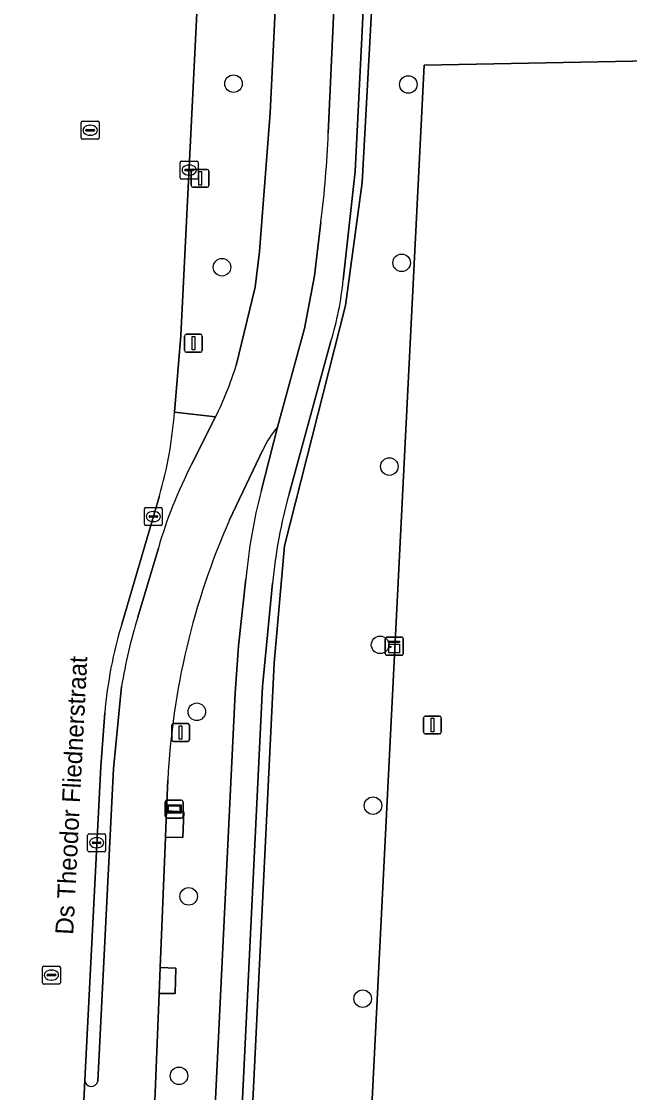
# Model space of a CAD drawing. Extents: x 161758 to 162722, y 384793 to 385405.
# Drawn here: x 162127.8 to 162161.7, y 385280.9 to 385340.7 of the extents above; entities that cross this region are included whole.
import ezdxf

# ---------------------------------------------------------------- set-up
doc = ezdxf.new("R2010")
doc.units = 0
for name, color, linetype in [('IMGEO_Berm_groen', 7, 'Continuous'), ('IMGEO_Boom', 7, 'Continuous'), ('IMGEO_Fietspad_gesloten', 7, 'Continuous'), ('IMGEO_Groenvoorziening', 7, 'Continuous'), ('IMGEO_Hek', 7, 'Continuous'), ('IMGEO_Kast', 7, 'Continuous'), ('IMGEO_Kolk', 7, 'Continuous'), ('IMGEO_Lichtmast', 7, 'Continuous'), ('IMGEO_Openbare_ruimte_label', 7, 'Continuous'), ('IMGEO_Rijbaan_lokaal_gesloten', 7, 'Continuous'), ('IMGEO_Rioolput', 7, 'Continuous'), ('IMGEO_Terreindeel_open', 7, 'Continuous'), ('IMGEO_Verkeersbordpaal', 7, 'Continuous'), ('IMGEO_Verkeerseiland_open', 7, 'Continuous'), ('IMGEO_Voetpad_open', 7, 'Continuous'), ('IMGEO_Wegwijzer', 7, 'Continuous')]:
    doc.layers.add(name, color=color, linetype=linetype)

msp = doc.modelspace()

# ---------------------------------------------------------------- linework, layer by layer
at = {"layer": 'IMGEO_Berm_groen'}
for points in [[(162138.352, 385356.061), (162138.078, 385350.894), (162136.706, 385323.145), (162136.346, 385318.869), (162138.638, 385318.607)], [(162139.783, 385321.485), (162140.845, 385325.839), (162141.092, 385327.83), (162141.672, 385335.573), (162142.271, 385347.778)], [(162141.17, 385314.469), (162142.089, 385318.047)], [(162141.277, 385316.771), (162139.414, 385312.866)], [(162139.724, 385303.205), (162139.916, 385305.842), (162140.326, 385309.592)], [(162135.97, 385298.369), (162135.902, 385296.656), (162136.872, 385296.597), (162136.811, 385295.159), (162135.843, 385295.176), (162135.553, 385287.905), (162136.417, 385287.87), (162136.38, 385286.457), (162135.496, 385286.459), (162135.129, 385277.251), (162134.787, 385270.387), (162138.123, 385270.221), (162139.724, 385303.205)]]:
    msp.add_lwpolyline(points, dxfattribs=at)
for centre, radius, start, end in [((162120.972, 385327.302), 19.69, 333.79389, 342.81627), ((162146.167, 385314.556), 5.368, 139.43026, 155.62736), ((162172.317, 385306.567), 32.134, 165.76484, 174.59875), ((162176.927, 385296.297), 41.01, 156.16908, 177.10328)]:
    msp.add_arc(centre, radius, start, end, dxfattribs=at)
at = {"layer": 'IMGEO_Boom'}
for centre in [(162139.634, 385337.193), (162149.378, 385337.145), (162149.005, 385327.204), (162138.998, 385326.956), (162148.319, 385315.843), (162147.806, 385305.902), (162137.589, 385302.172), (162147.413, 385296.939), (162137.138, 385291.878), (162146.832, 385286.174), (162136.595, 385281.876)]:
    msp.add_circle(centre, 0.489, dxfattribs=at)
at = {"layer": 'IMGEO_Fietspad_gesloten'}
for points in [[(162144.918, 385334.435), (162145.502, 385347.426), (162145.726, 385349.837), (162142.207, 385350.248), (162142.271, 385347.778), (162141.672, 385335.573), (162141.092, 385327.83), (162140.845, 385325.839), (162139.783, 385321.485)], [(162142.089, 385318.047), (162143.594, 385323.536), (162144.145, 385326.47), (162144.509, 385329.468)], [(162138.638, 385318.607), (162137.294, 385315.952)], [(162139.414, 385312.866), (162141.277, 385316.771)], [(162135.45, 385311.302), (162134.299, 385307.45)], [(162133.395, 385303.575), (162132.954, 385298.991), (162132.066, 385281.578)], [(162132.096, 385277.332), (162135.129, 385277.251), (162135.496, 385286.459), (162135.553, 385287.905), (162135.843, 385295.176), (162135.902, 385296.656), (162135.97, 385298.369)], [(162131.344, 385281.63), (162131.151, 385277.397)]]:
    msp.add_lwpolyline(points, dxfattribs=at)
for centre, radius, start, end in [((162086.015, 385336.785), 58.95, 352.86997, 357.7154), ((162120.972, 385327.302), 19.69, 333.79389, 342.81627), ((162146.167, 385314.556), 5.368, 139.43026, 155.62736), ((162160.039, 385304.242), 25.582, 152.75806, 163.97943), ((162176.927, 385296.297), 41.01, 156.16908, 177.10328), ((162164.556, 385298.348), 31.596, 163.2582, 170.47843), ((162131.708, 385281.644), 0.364, 182.24351, 349.51758)]:
    msp.add_arc(centre, radius, start, end, dxfattribs=at)
at = {"layer": 'IMGEO_Groenvoorziening'}
for points in [[(162141.818, 385309.344), (162141.256, 385303.578), (162138.882, 385254.554), (162134.904, 385254.707), (162126.688, 385089.939), (162123.507, 385021.46), (162127.975, 385021.202), (162128.056, 385022.862), (162131.31, 385089.036), (162131.34, 385089.671), (162131.648, 385095.933), (162131.658, 385096.124), (162133.367, 385130.823), (162139.214, 385249.548), (162141.898, 385304.88), (162142.47, 385311.424), (162145.872, 385324.819), (162146.81, 385331.678), (162147.884, 385351.44), (162211.124, 385352.462)], [(162211.124, 385352.462), (162147.884, 385351.44), (162146.81, 385331.678), (162145.872, 385324.819), (162142.47, 385311.424), (162141.898, 385304.88), (162139.214, 385249.548), (162133.367, 385130.823), (162139.817, 385130.505), (162150.256, 385338.217), (162211.326, 385339.4)], [(162147.19, 385348.002), (162146.419, 385332.292), (162145.754, 385326.254)], [(162211.326, 385339.4), (162150.256, 385338.217), (162139.817, 385130.505), (162139.433, 385122.857), (162137.997, 385095.888), (162138.195, 385088.671), (162134.073, 385009.395), (162135.55, 385009.336), (162149.437, 385008.779), (162272.675, 385003.936)], [(162145.067, 385322.828), (162142.737, 385314.33)]]:
    msp.add_lwpolyline(points, dxfattribs=at)
for centre, radius, start, end in [((162127.687, 385328.095), 18.161, 343.14065, 354.1816), ((162169.832, 385306.758), 28.133, 164.38692, 174.72643)]:
    msp.add_arc(centre, radius, start, end, dxfattribs=at)
at = {"layer": 'IMGEO_Hek'}
msp.add_lwpolyline([(162147.884, 385351.44), (162146.81, 385331.678), (162145.872, 385324.819), (162142.47, 385311.424), (162141.898, 385304.88), (162139.214, 385249.548)], dxfattribs=at)
at = {"layer": 'IMGEO_Kast'}
for p, q in [((162148.097, 385305.402), (162148.097, 385306.243)), ((162148.097, 385306.243), (162148.097, 385305.402)), ((162148.172, 385306.327), (162149.013, 385306.327)), ((162149.013, 385306.327), (162148.172, 385306.327)), ((162149.097, 385306.252), (162149.097, 385305.411)), ((162149.097, 385305.411), (162149.097, 385306.252)), ((162149.022, 385305.327), (162148.181, 385305.327)), ((162148.181, 385305.327), (162149.022, 385305.327))]:
    msp.add_line(p, q, dxfattribs=at)
for points in [[(162148.292, 385306.117), (162148.892, 385306.117), (162148.892, 385306.032), (162148.292, 385306.032), (162148.292, 385306.117)], [(162148.292, 385305.942), (162148.892, 385305.942), (162148.892, 385305.453), (162148.292, 385305.453), (162148.292, 385305.942)]]:
    msp.add_lwpolyline(points, dxfattribs=at)
msp.add_circle((162148.376, 385305.791), 0.0377, dxfattribs=at)
for centre, start, end in [((162148.175, 385306.249), 92.4484, 184.28452), ((162148.175, 385306.249), 92.4484, 184.28452), ((162149.019, 385306.249), 2.4484, 94.28452), ((162149.019, 385306.249), 2.4484, 94.28452), ((162148.175, 385305.405), 182.4484, 274.28452), ((162148.175, 385305.405), 182.4484, 274.28452), ((162149.019, 385305.405), 272.4484, 4.28452), ((162149.019, 385305.405), 272.4484, 4.28452)]:
    msp.add_arc(centre, 0.0779, start, end, dxfattribs=at)
at = {"layer": 'IMGEO_Kolk'}
for p, q in [((162136.667, 385331.949), (162136.667, 385332.801)), ((162136.742, 385332.875), (162137.594, 385332.875)), ((162137.155, 385332.655), (162137.18, 385332.655)), ((162137.668, 385332.801), (162137.668, 385331.949)), ((162137.594, 385331.875), (162136.742, 385331.875)), ((162136.926, 385332.369), (162136.926, 385332.381)), ((162137.364, 385332.332), (162136.966, 385332.332)), ((162136.969, 385332.418), (162137.367, 385332.418)), ((162137.178, 385332.095), (162137.153, 385332.095)), ((162137.41, 385332.381), (162137.41, 385332.369)), ((162134.667, 385312.631), (162134.667, 385313.483)), ((162134.742, 385313.557), (162135.594, 385313.557)), ((162135.155, 385313.337), (162135.18, 385313.337)), ((162135.668, 385313.483), (162135.668, 385312.631)), ((162134.926, 385313.051), (162134.926, 385313.063)), ((162135.364, 385313.014), (162134.966, 385313.014)), ((162134.969, 385313.1), (162135.367, 385313.1)), ((162135.178, 385312.777), (162135.153, 385312.777)), ((162135.41, 385313.063), (162135.41, 385313.051)), ((162135.594, 385312.557), (162134.742, 385312.557)), ((162131.507, 385294.441), (162131.507, 385295.293)), ((162131.582, 385295.367), (162132.434, 385295.367)), ((162131.766, 385294.861), (162131.766, 385294.873)), ((162132.204, 385294.824), (162131.806, 385294.824)), ((162131.809, 385294.91), (162132.207, 385294.91)), ((162131.995, 385295.147), (162132.02, 385295.147)), ((162132.25, 385294.873), (162132.25, 385294.861)), ((162132.508, 385295.293), (162132.508, 385294.441)), ((162132.434, 385294.367), (162131.582, 385294.367)), ((162132.018, 385294.587), (162131.993, 385294.587))]:
    msp.add_line(p, q, dxfattribs=at)
for points in [[(162136.667, 385331.949), (162136.667, 385332.801)], [(162136.742, 385332.875), (162137.594, 385332.875)], [(162137.668, 385332.801), (162137.668, 385331.949)], [(162137.594, 385331.875), (162136.742, 385331.875)], [(162134.667, 385312.631), (162134.667, 385313.483)], [(162134.742, 385313.557), (162135.594, 385313.557)], [(162135.668, 385313.483), (162135.668, 385312.631)], [(162135.594, 385312.557), (162134.742, 385312.557)], [(162131.507, 385294.441), (162131.507, 385295.293)], [(162131.582, 385295.367), (162132.434, 385295.367)], [(162132.508, 385295.293), (162132.508, 385294.441)], [(162132.434, 385294.367), (162131.582, 385294.367)]]:
    msp.add_lwpolyline(points, dxfattribs=at)
for centre, radius, start, end in [((162136.744, 385332.799), 0.0765, 91.55205, 178.44795), ((162136.744, 385332.799), 0.0765, 91.55205, 178.44795), ((162137.592, 385332.799), 0.0765, 1.55205, 88.44795), ((162137.592, 385332.799), 0.0765, 1.55205, 88.44795), ((162136.744, 385331.951), 0.0765, 181.55205, 268.44795), ((162136.744, 385331.951), 0.0765, 181.55205, 268.44795), ((162136.966, 385332.378), 0.0403, 85.87752, 175.75265), ((162136.963, 385332.368), 0.0366, 178.93798, 274.71019), ((162137.367, 385332.375), 0.043, 264.86636, 352.45326), ((162137.371, 385332.38), 0.0386, 1.73085, 96.63898), ((162137.592, 385331.951), 0.0765, 271.55205, 358.44795), ((162137.592, 385331.951), 0.0765, 271.55205, 358.44795), ((162134.744, 385313.481), 0.0765, 91.55205, 178.44795), ((162134.744, 385313.481), 0.0765, 91.55205, 178.44795), ((162135.592, 385313.481), 0.0765, 1.55205, 88.44795), ((162135.592, 385313.481), 0.0765, 1.55205, 88.44795), ((162134.966, 385313.06), 0.0403, 85.87752, 175.75265), ((162134.963, 385313.05), 0.0366, 178.93798, 274.71019), ((162135.367, 385313.057), 0.043, 264.86636, 352.45326), ((162135.371, 385313.062), 0.0386, 1.73085, 96.63898), ((162134.744, 385312.633), 0.0765, 181.55205, 268.44795), ((162134.744, 385312.633), 0.0765, 181.55205, 268.44795), ((162135.592, 385312.633), 0.0765, 271.55205, 358.44795), ((162135.592, 385312.633), 0.0765, 271.55205, 358.44795), ((162131.584, 385295.291), 0.0765, 91.55205, 178.44795), ((162131.584, 385295.291), 0.0765, 91.55205, 178.44795), ((162131.806, 385294.87), 0.0403, 85.87752, 175.75265), ((162131.803, 385294.86), 0.0366, 178.93798, 274.71019), ((162132.207, 385294.867), 0.043, 264.86636, 352.45326), ((162132.211, 385294.872), 0.0386, 1.73085, 96.63898), ((162132.432, 385295.291), 0.0765, 1.55205, 88.44795), ((162132.432, 385295.291), 0.0765, 1.55205, 88.44795), ((162131.584, 385294.443), 0.0765, 181.55205, 268.44795), ((162131.584, 385294.443), 0.0765, 181.55205, 268.44795), ((162132.432, 385294.443), 0.0765, 271.55205, 358.44795), ((162132.432, 385294.443), 0.0765, 271.55205, 358.44795)]:
    msp.add_arc(centre, radius, start, end, dxfattribs=at)
for centre, major_axis, ratio, start_param, end_param in [((162137.154, 385332.375), (-0.387, 0.002), 0.722429, 4.712389, 7.853982), ((162137.179, 385332.375), (-0.39, 0.002), 0.717154, 1.570796, 4.712389), ((162135.154, 385313.057), (-0.387, 0.002), 0.722429, 4.712389, 7.853982), ((162135.179, 385313.057), (-0.39, 0.002), 0.717154, 1.570796, 4.712389), ((162131.994, 385294.867), (-0.387, 0.002), 0.722429, 4.712389, 7.853982), ((162132.019, 385294.867), (-0.39, 0.002), 0.717154, 1.570796, 4.712389)]:
    msp.add_ellipse(centre, major_axis=major_axis, ratio=ratio, start_param=start_param, end_param=end_param, dxfattribs=at)
at = {"layer": 'IMGEO_Lichtmast'}
for p, q in [((162136.907, 385322.318), (162136.907, 385323.118)), ((162136.907, 385323.118), (162136.907, 385322.318)), ((162137.007, 385323.218), (162137.797, 385323.218)), ((162137.797, 385323.218), (162137.007, 385323.218)), ((162137.897, 385323.118), (162137.897, 385322.318)), ((162137.897, 385322.318), (162137.897, 385323.118)), ((162137.797, 385322.218), (162137.007, 385322.218)), ((162137.007, 385322.218), (162137.797, 385322.218)), ((162136.192, 385300.616), (162136.192, 385301.416)), ((162136.192, 385301.416), (162136.192, 385300.616)), ((162136.292, 385301.516), (162137.082, 385301.516)), ((162137.082, 385301.516), (162136.292, 385301.516)), ((162137.182, 385301.416), (162137.182, 385300.616)), ((162137.182, 385300.616), (162137.182, 385301.416)), ((162150.225, 385301.034), (162150.225, 385301.834)), ((162150.225, 385301.834), (162150.225, 385301.034)), ((162150.325, 385301.934), (162151.115, 385301.934)), ((162151.115, 385301.934), (162150.325, 385301.934)), ((162151.215, 385301.834), (162151.215, 385301.034)), ((162151.215, 385301.034), (162151.215, 385301.834)), ((162151.115, 385300.934), (162150.325, 385300.934)), ((162150.325, 385300.934), (162151.115, 385300.934)), ((162137.082, 385300.516), (162136.292, 385300.516)), ((162136.292, 385300.516), (162137.082, 385300.516))]:
    msp.add_line(p, q, dxfattribs=at)
for points in [[(162137.327, 385323.093), (162137.477, 385323.093), (162137.477, 385322.343), (162137.327, 385322.343), (162137.327, 385323.093)], [(162136.612, 385301.391), (162136.762, 385301.391), (162136.762, 385300.641), (162136.612, 385300.641), (162136.612, 385301.391)], [(162150.645, 385301.809), (162150.795, 385301.809), (162150.795, 385301.059), (162150.645, 385301.059), (162150.645, 385301.809)]]:
    msp.add_lwpolyline(points, dxfattribs=at)
for centre, start, end in [((162137.007, 385323.118), 90, 180), ((162137.007, 385323.118), 90, 180), ((162137.797, 385323.118), 0, 90), ((162137.797, 385323.118), 360, 90), ((162137.007, 385322.318), 180, 270), ((162137.007, 385322.318), 180, 270), ((162137.797, 385322.318), 270, 0), ((162137.797, 385322.318), 270, 0), ((162136.292, 385301.416), 90, 180), ((162136.292, 385301.416), 90, 180), ((162137.082, 385301.416), 0, 90), ((162137.082, 385301.416), 360, 90), ((162150.325, 385301.834), 90, 180), ((162150.325, 385301.834), 90, 180), ((162151.115, 385301.834), 0, 90), ((162151.115, 385301.834), 360, 90), ((162150.325, 385301.034), 180, 270), ((162150.325, 385301.034), 180, 270), ((162151.115, 385301.034), 270, 0), ((162151.115, 385301.034), 270, 0), ((162136.292, 385300.616), 180, 270), ((162136.292, 385300.616), 180, 270), ((162137.082, 385300.616), 270, 0), ((162137.082, 385300.616), 270, 0)]:
    msp.add_arc(centre, 0.1, start, end, dxfattribs=at)
at = {"layer": 'IMGEO_Rijbaan_lokaal_gesloten'}
for points in [[(162136.346, 385318.869), (162136.706, 385323.145), (162138.078, 385350.894), (162138.352, 385356.061), (162138.553, 385360.466), (162125.588, 385360.595), (162125.801, 385360.29), (162125.941, 385359.83)], [(162133.404, 385307.058), (162135.513, 385314.217)], [(162128.368, 385221.63), (162128.609, 385226.485), (162130.853, 385272.55), (162131.151, 385277.397), (162131.344, 385281.63), (162132.238, 385299.116), (162132.459, 385302.12)]]:
    msp.add_lwpolyline(points, dxfattribs=at)
for centre, radius, start, end in [((162112.773, 385320.69), 23.644, 344.11222, 355.58387), ((162157.345, 385299.917), 24.983, 163.39122, 174.94103)]:
    msp.add_arc(centre, radius, start, end, dxfattribs=at)
at = {"layer": 'IMGEO_Rioolput'}
for p, q in [((162131.148, 385334.169), (162131.148, 385335.021)), ((162131.223, 385335.095), (162132.075, 385335.095)), ((162131.636, 385334.875), (162131.661, 385334.875)), ((162132.149, 385335.021), (162132.149, 385334.169)), ((162131.407, 385334.589), (162131.407, 385334.601)), ((162131.845, 385334.552), (162131.447, 385334.552)), ((162131.45, 385334.638), (162131.848, 385334.638)), ((162131.659, 385334.315), (162131.634, 385334.315)), ((162131.891, 385334.601), (162131.891, 385334.589)), ((162132.075, 385334.095), (162131.223, 385334.095)), ((162128.985, 385287.067), (162128.985, 385287.919)), ((162129.06, 385287.993), (162129.912, 385287.993)), ((162129.473, 385287.773), (162129.498, 385287.773)), ((162129.986, 385287.919), (162129.986, 385287.067)), ((162129.244, 385287.487), (162129.244, 385287.499)), ((162129.682, 385287.45), (162129.284, 385287.45)), ((162129.287, 385287.536), (162129.685, 385287.536)), ((162129.496, 385287.213), (162129.471, 385287.213)), ((162129.728, 385287.499), (162129.728, 385287.487)), ((162129.912, 385286.993), (162129.06, 385286.993))]:
    msp.add_line(p, q, dxfattribs=at)
for points in [[(162131.148, 385334.169), (162131.148, 385335.021)], [(162131.223, 385335.095), (162132.075, 385335.095)], [(162132.149, 385335.021), (162132.149, 385334.169)], [(162132.075, 385334.095), (162131.223, 385334.095)], [(162128.985, 385287.067), (162128.985, 385287.919)], [(162129.06, 385287.993), (162129.912, 385287.993)], [(162129.986, 385287.919), (162129.986, 385287.067)], [(162129.912, 385286.993), (162129.06, 385286.993)]]:
    msp.add_lwpolyline(points, dxfattribs=at)
for centre, radius, start, end in [((162131.225, 385335.019), 0.0765, 91.55205, 178.44795), ((162131.225, 385335.019), 0.0765, 91.55205, 178.44795), ((162132.073, 385335.019), 0.0765, 1.55205, 88.44795), ((162132.073, 385335.019), 0.0765, 1.55205, 88.44795), ((162131.447, 385334.598), 0.0403, 85.87752, 175.75265), ((162131.444, 385334.588), 0.0366, 178.93798, 274.71019), ((162131.848, 385334.595), 0.043, 264.86636, 352.45326), ((162131.852, 385334.6), 0.0386, 1.73085, 96.63898), ((162131.225, 385334.171), 0.0765, 181.55205, 268.44795), ((162131.225, 385334.171), 0.0765, 181.55205, 268.44795), ((162132.073, 385334.171), 0.0765, 271.55205, 358.44795), ((162132.073, 385334.171), 0.0765, 271.55205, 358.44795), ((162129.062, 385287.917), 0.0765, 91.55205, 178.44795), ((162129.062, 385287.917), 0.0765, 91.55205, 178.44795), ((162129.91, 385287.917), 0.0765, 1.55205, 88.44795), ((162129.91, 385287.917), 0.0765, 1.55205, 88.44795), ((162129.062, 385287.069), 0.0765, 181.55205, 268.44795), ((162129.062, 385287.069), 0.0765, 181.55205, 268.44795), ((162129.284, 385287.496), 0.0403, 85.87752, 175.75265), ((162129.281, 385287.486), 0.0366, 178.93798, 274.71019), ((162129.685, 385287.493), 0.043, 264.86636, 352.45326), ((162129.689, 385287.498), 0.0386, 1.73085, 96.63898), ((162129.91, 385287.069), 0.0765, 271.55205, 358.44795), ((162129.91, 385287.069), 0.0765, 271.55205, 358.44795)]:
    msp.add_arc(centre, radius, start, end, dxfattribs=at)
for centre, major_axis, ratio, start_param, end_param in [((162131.635, 385334.595), (-0.387, 0.002), 0.722429, 4.712389, 7.853982), ((162131.66, 385334.595), (-0.39, 0.002), 0.717154, 1.570796, 4.712389), ((162129.472, 385287.493), (-0.387, 0.002), 0.722429, 4.712389, 7.853982), ((162129.497, 385287.493), (-0.39, 0.002), 0.717154, 1.570796, 4.712389)]:
    msp.add_ellipse(centre, major_axis=major_axis, ratio=ratio, start_param=start_param, end_param=end_param, dxfattribs=at)
at = {"layer": 'IMGEO_Terreindeel_open'}
for points in [[(162135.902, 385296.656), (162135.843, 385295.176), (162136.811, 385295.159), (162136.872, 385296.597)], [(162135.496, 385286.459), (162136.38, 385286.457), (162136.417, 385287.87), (162135.553, 385287.905)]]:
    msp.add_lwpolyline(points, close=True, dxfattribs=at)
at = {"layer": 'IMGEO_Verkeersbordpaal'}
for p, q in [((162137.275, 385331.512), (162137.275, 385332.312)), ((162137.275, 385332.312), (162137.275, 385331.512)), ((162137.375, 385332.412), (162138.165, 385332.412)), ((162138.165, 385332.412), (162137.375, 385332.412)), ((162138.265, 385332.312), (162138.265, 385331.512)), ((162138.265, 385331.512), (162138.265, 385332.312)), ((162138.165, 385331.412), (162137.375, 385331.412)), ((162137.375, 385331.412), (162138.165, 385331.412))]:
    msp.add_line(p, q, dxfattribs=at)
msp.add_lwpolyline([(162137.695, 385332.287), (162137.845, 385332.287), (162137.845, 385331.537), (162137.695, 385331.537), (162137.695, 385332.287)], dxfattribs=at)
for centre, start, end in [((162137.375, 385332.312), 90, 180), ((162137.375, 385332.312), 90, 180), ((162138.165, 385332.312), 0, 90), ((162138.165, 385332.312), 360, 90), ((162137.375, 385331.512), 180, 270), ((162137.375, 385331.512), 180, 270), ((162138.165, 385331.512), 270, 0), ((162138.165, 385331.512), 270, 0)]:
    msp.add_arc(centre, 0.1, start, end, dxfattribs=at)
at = {"layer": 'IMGEO_Verkeerseiland_open'}
for points in [[(162137.294, 385315.952), (162138.638, 385318.607), (162136.346, 385318.869)], [(162135.513, 385314.217), (162133.404, 385307.058)], [(162134.299, 385307.45), (162135.45, 385311.302)], [(162132.066, 385281.578), (162132.954, 385298.991), (162133.395, 385303.575)], [(162132.459, 385302.12), (162132.238, 385299.116), (162131.344, 385281.63)]]:
    msp.add_lwpolyline(points, dxfattribs=at)
for centre, radius, start, end in [((162112.773, 385320.69), 23.644, 344.11222, 355.58387), ((162160.039, 385304.242), 25.582, 152.75806, 163.97943), ((162164.556, 385298.348), 31.596, 163.2582, 170.47843), ((162157.345, 385299.917), 24.983, 163.39122, 174.94103), ((162131.708, 385281.644), 0.364, 182.24351, 349.51758)]:
    msp.add_arc(centre, radius, start, end, dxfattribs=at)
at = {"layer": 'IMGEO_Voetpad_open'}
for points in [[(162145.726, 385349.837), (162145.502, 385347.426), (162144.918, 385334.435)], [(162145.754, 385326.254), (162146.419, 385332.292), (162147.19, 385348.002)], [(162144.509, 385329.468), (162144.145, 385326.47), (162143.594, 385323.536), (162142.089, 385318.047), (162141.17, 385314.469)], [(162142.737, 385314.33), (162145.067, 385322.828)], [(162140.326, 385309.592), (162139.916, 385305.842), (162139.724, 385303.205), (162138.123, 385270.221), (162134.787, 385270.387), (162134.197, 385258.252), (162134.018, 385254.741), (162134.904, 385254.707), (162138.882, 385254.554), (162141.256, 385303.578), (162141.818, 385309.344)]]:
    msp.add_lwpolyline(points, dxfattribs=at)
for centre, radius, start, end in [((162086.015, 385336.785), 58.95, 352.86997, 357.7154), ((162127.687, 385328.095), 18.161, 343.14065, 354.1816), ((162172.317, 385306.567), 32.134, 165.76484, 174.59875), ((162169.832, 385306.758), 28.133, 164.38692, 174.72643)]:
    msp.add_arc(centre, radius, start, end, dxfattribs=at)
at = {"layer": 'IMGEO_Wegwijzer'}
for p, q in [((162135.932, 385297.248), (162136.722, 385297.248)), ((162136.722, 385297.248), (162135.932, 385297.248)), ((162135.832, 385296.348), (162135.832, 385297.148)), ((162135.832, 385297.148), (162135.832, 385296.348)), ((162136.822, 385297.148), (162136.822, 385296.348)), ((162136.822, 385296.348), (162136.822, 385297.148)), ((162136.722, 385296.248), (162135.932, 385296.248)), ((162135.932, 385296.248), (162136.722, 385296.248))]:
    msp.add_line(p, q, dxfattribs=at)
for points in [[(162135.933, 385296.98), (162136.721, 385296.98), (162136.721, 385296.516), (162135.933, 385296.516), (162135.933, 385296.98)], [(162135.998, 385296.915), (162135.998, 385296.581), (162136.656, 385296.581), (162136.656, 385296.915), (162135.998, 385296.915)]]:
    msp.add_lwpolyline(points, dxfattribs=at)
for centre, start, end in [((162135.932, 385297.148), 90, 180), ((162135.932, 385297.148), 90, 180), ((162136.722, 385297.148), 0, 90), ((162136.722, 385297.148), 360, 90), ((162135.932, 385296.348), 180, 270), ((162135.932, 385296.348), 180, 270), ((162136.722, 385296.348), 270, 0), ((162136.722, 385296.348), 270, 0)]:
    msp.add_arc(centre, 0.1, start, end, dxfattribs=at)

# ---------------------------------------------------------------- texts
at = {"layer": 'IMGEO_Openbare_ruimte_label'}
msp.add_text('Ds Theodor Fliednerstraat', height=1, rotation=87.07753, dxfattribs=at).set_placement((162130.7, 385289.727))

doc.saveas('drawing.dxf')
